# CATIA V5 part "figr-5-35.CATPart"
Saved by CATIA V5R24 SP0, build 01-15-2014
Part number: Part1
Bounding box of the stored display mesh (mm): x -39.481 to 85.69, y 0 to 131.399, z 0 to 44
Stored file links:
  D:\KAVITA\CATIA V5-6R2014 Project_ Kavita\CATIA V5-6R2014_partfiles\Partfiles\c05_catia_v5-6r2014_prt\figr-5-35.CATPart
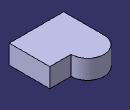
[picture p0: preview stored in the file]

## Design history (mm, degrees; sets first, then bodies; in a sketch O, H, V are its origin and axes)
Body1 (main body)
  Sketch1 on xy-plane, origin (0, 0, 0), H (1, 0, 0), V (0, 1, 0)
    point P1 (-39.4814, 0)
    line L1 (-39.4814, 0) -> (36.6898, 0)
    line L2 (36.6898, 0) -> (36.6898, 93.3015)
    arc A1 centre (-1.4186, 93.3015) radius 38.1084 from (36.6898, 93.3015) to (-39.4814, 95.1659) ccw
    line L3 (-39.4814, 95.1659) -> (-39.4814, 0)
    coincidence: P1 H
    horizontal: L1 H
    vertical: L2 V, L3 V
    tangency: A1 L2
  Pad1: profile Sketch1, direction (0, 0, 1), length 44
  Pad2: profile face of Pad1, direction along edge [face of Pad1 | face of Pad1] reversed, length -49, opposite side length -19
